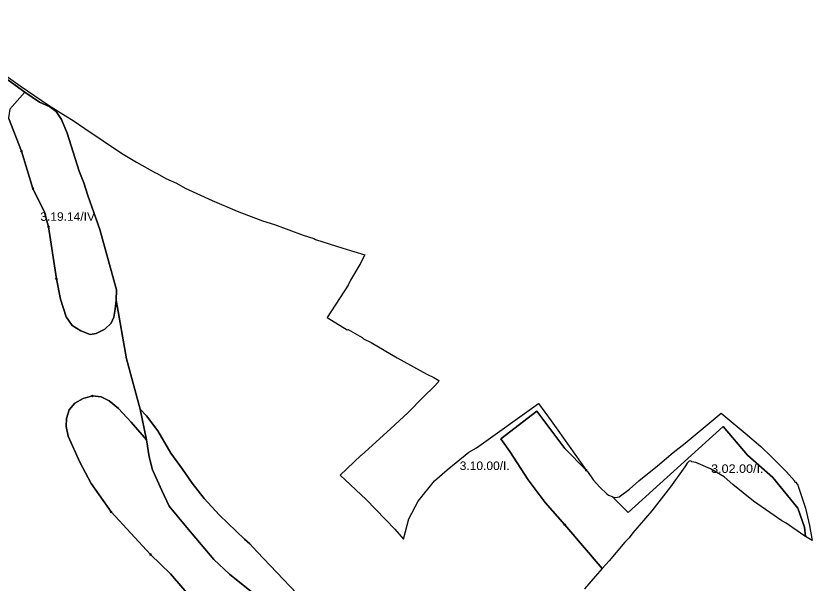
# Model space of a CAD drawing. Extents: x -650455 to -642254, y -1075222 to -1066610.
# Drawn here: x -644416 to -643484, y -1072701 to -1072036 of the extents above; entities that cross this region are included whole.
import ezdxf
from ezdxf.enums import TextEntityAlignment as Align

# ---------------------------------------------------------------- set-up
doc = ezdxf.new("R2010")
doc.units = 0
doc.header["$LTSCALE"] = 4
doc.header["$PDMODE"] = 32
doc.header["$PDSIZE"] = 2
for name, color, linetype, lineweight in [('1', 7, 'Continuous', 25), ('11', 7, 'Continuous', 13), ('13', 7, 'Continuous', 13), ('14', 7, 'Continuous', 13)]:
    doc.layers.add(name, color=color, linetype=linetype, lineweight=lineweight)
doc.layers.add('2', color=7, linetype='Continuous')

msp = doc.modelspace()

# ---------------------------------------------------------------- linework, layer by layer
at = {"layer": '1'}
for points in [[(-644538.207, -1072030.496), (-644520.385, -1072042.196), (-644480.817, -1072072.875), (-644437.149, -1072103.18), (-644405.404, -1072125.733), (-644423.152, -1072145.492), (-644424.551, -1072155.634), (-644409.426, -1072194.802), (-644395.962, -1072238.516), (-644382.411, -1072266.143), (-644377.69, -1072283.279), (-644368.51, -1072344.479), (-644363.526, -1072367.91), (-644357.056, -1072388.717), (-644349.887, -1072398.859), (-644340.095, -1072405.329), (-644329.079, -1072409.525), (-644322.085, -1072408.476), (-644311.769, -1072403.231), (-644304.425, -1072396.061), (-644301.277, -1072389.242), (-644299.529, -1072379.975), (-644298.392, -1072369.308), (-644286.239, -1072437.852)], [(-644438.697, -1072098.552), (-644410.923, -1072118.41), (-644377.621, -1072140.846), (-644357.865, -1072153.546), (-644348.692, -1072158.767), (-644335.287, -1072168.363), (-644292.247, -1072197.151), (-644274.89, -1072207.593), (-644252.594, -1072220.293), (-644250.619, -1072220.858), (-644240.176, -1072226.643), (-644227.758, -1072232.429), (-644217.598, -1072237.932), (-644186.271, -1072252.607), (-644156.637, -1072265.167), (-644127.004, -1072276.455), (-644113.174, -1072280.831), (-644079.59, -1072293.107), (-644067.172, -1072296.917), (-644065.196, -1072298.046), (-644033.064, -1072308.452), (-644007.321, -1072316.245), (-644012.984, -1072327.397), (-644023.991, -1072346.024), (-644026.954, -1072351.811), (-644051.306, -1072389.703)], [(-644286.239, -1072437.852), (-644298.392, -1072369.308), (-644298.305, -1072357.068), (-644317.801, -1072286.426), (-644331.79, -1072246.559), (-644336.423, -1072231.696), (-644342.019, -1072218.058), (-644355.745, -1072173.819), (-644362.564, -1072157.557), (-644368.859, -1072148.465), (-644376.028, -1072142.869), (-644388.268, -1072137.274), (-644405.404, -1072125.733), (-644437.149, -1072103.18)], [(-644423.152, -1072145.492), (-644405.404, -1072125.733), (-644388.268, -1072137.274), (-644376.028, -1072142.869), (-644368.859, -1072148.465), (-644362.564, -1072157.557), (-644355.745, -1072173.819), (-644342.019, -1072218.058), (-644336.423, -1072231.696), (-644331.79, -1072246.559), (-644317.801, -1072286.426), (-644298.305, -1072357.068), (-644298.392, -1072369.308), (-644299.529, -1072379.975), (-644301.277, -1072389.242), (-644304.425, -1072396.061), (-644311.769, -1072403.231), (-644322.085, -1072408.476), (-644329.079, -1072409.525), (-644340.095, -1072405.329), (-644349.887, -1072398.859), (-644357.056, -1072388.717), (-644363.526, -1072367.91), (-644368.51, -1072344.479), (-644377.69, -1072283.279), (-644382.411, -1072266.143), (-644395.962, -1072238.516), (-644409.426, -1072194.802), (-644424.551, -1072155.634)], [(-644051.306, -1072389.703), (-644027.942, -1072403.881), (-644026.672, -1072403.74), (-644010.585, -1072413.194), (-644009.033, -1072414.464), (-644000.002, -1072418.98), (-643969.521, -1072436.761), (-643934.525, -1072455.951), (-643926.622, -1072459.761), (-643920.696, -1072463.432), (-643921.401, -1072465.266), (-643926.058, -1072470.487), (-643938.758, -1072482.623), (-643956.68, -1072500.684), (-643977.282, -1072520.158), (-644011.29, -1072550.922), (-644011.982, -1072551.178), (-644036.381, -1072574.279), (-644005.928, -1072602.71), (-643972.061, -1072637.565), (-643961.833, -1072649.254), (-643955.722, -1072625.442), (-643944.831, -1072604.597), (-643925.552, -1072581.035), (-643910.943, -1072568.102), (-643885.377, -1072547.293), (-643876.387, -1072542.172), (-643804.01, -1072490.458), (-643789.037, -1072510.422), (-643785.368, -1072516.208), (-643781.276, -1072521.428), (-643748.01, -1072568.45), (-643773.195, -1072543.057), (-643805.894, -1072499.343), (-643848.034, -1072531.866), (-643837.543, -1072546.38), (-643816.123, -1072579.777), (-643796.189, -1072606.18), (-643773.108, -1072632.234), (-643729.268, -1072683.464)], [(-644286.239, -1072437.852), (-644270.415, -1072497.128), (-644262.896, -1072532.799), (-644280.783, -1072512.218), (-644295.821, -1072496.306), (-644306.662, -1072487.214), (-644316.279, -1072482.492), (-644326.42, -1072481.443), (-644337.262, -1072484.591), (-644347.053, -1072490.011), (-644353.523, -1072497.705), (-644356.846, -1072507.847), (-644357.02, -1072517.289), (-644354.572, -1072528.48), (-644341.108, -1072559.08), (-644327.819, -1072584.084), (-644304.476, -1072617.307), (-644258.227, -1072667.141), (-644234.796, -1072689.872), (-644186.973, -1072745.651)], [(-644087.515, -1072712.377), (-644133.59, -1072663.941), (-644141.983, -1072654.499), (-644148.278, -1072649.253), (-644177.392, -1072620.927), (-644195.402, -1072601.518), (-644209.565, -1072583.682), (-644221.018, -1072567.071), (-644234.482, -1072548.536), (-644249.695, -1072522.483), (-644262.896, -1072504.647), (-644270.415, -1072497.128), (-644286.239, -1072437.852)], [(-644234.796, -1072689.872), (-644258.227, -1072667.141), (-644304.476, -1072617.307), (-644327.819, -1072584.084), (-644341.108, -1072559.08), (-644354.572, -1072528.48), (-644357.02, -1072517.289), (-644356.846, -1072507.847), (-644353.523, -1072497.705), (-644347.053, -1072490.011), (-644337.262, -1072484.591), (-644326.42, -1072481.443), (-644316.279, -1072482.492), (-644306.662, -1072487.214), (-644295.821, -1072496.306), (-644280.783, -1072512.218), (-644262.896, -1072532.799)], [(-644136.264, -1072714.177), (-644165.902, -1072690.047), (-644184.262, -1072673.086), (-644215.824, -1072635.667), (-644236.282, -1072610.662), (-644245.025, -1072592.302), (-644255.953, -1072567.997), (-644259.8, -1072552.61), (-644262.896, -1072532.799), (-644270.415, -1072497.128), (-644262.896, -1072504.647), (-644249.695, -1072522.483), (-644234.482, -1072548.536), (-644221.018, -1072567.071), (-644209.565, -1072583.682), (-644195.402, -1072601.518), (-644177.392, -1072620.927), (-644148.278, -1072649.253), (-644141.983, -1072654.499), (-644133.59, -1072663.941), (-644087.515, -1072712.377)], [(-643837.543, -1072546.38), (-643848.034, -1072531.866), (-643805.894, -1072499.343), (-643773.195, -1072543.057), (-643748.01, -1072568.45)], [(-643748.01, -1072568.45), (-643747.832, -1072568.701), (-643746.421, -1072570.113), (-643739.789, -1072579.849), (-643732.169, -1072588.175), (-643723.984, -1072596.077), (-643722.009, -1072597.489), (-643717.775, -1072599.322), (-643717.273, -1072599.44), (-643698.794, -1072618.071), (-643587.673, -1072517.179), (-643559.346, -1072550.751), (-643529.446, -1072576.979), (-643500.332, -1072612.825), (-643492.463, -1072635.207), (-643491.082, -1072646.002), (-643493.123, -1072644.762), (-643514.008, -1072630.508), (-643518.947, -1072627.546), (-643552.249, -1072604.544), (-643576.521, -1072585.212), (-643586.681, -1072576.322), (-643602.627, -1072567.008), (-643619.561, -1072559.529), (-643624.217, -1072558.682), (-643625.487, -1072557.272), (-643627.463, -1072557.836), (-643630.003, -1072560.234), (-643632.402, -1072564.467), (-643649.194, -1072588.034), (-643671.208, -1072615.974), (-643693.362, -1072641.657), (-643697.737, -1072647.724), (-643702.817, -1072652.664), (-643721.303, -1072674.677), (-643729.268, -1072683.464), (-643773.108, -1072632.234), (-643796.189, -1072606.18), (-643816.123, -1072579.777), (-643837.543, -1072546.38)], [(-644262.896, -1072532.799), (-644259.8, -1072552.61), (-644255.953, -1072567.997), (-644245.025, -1072592.302), (-644236.282, -1072610.662), (-644215.824, -1072635.667), (-644184.262, -1072673.086), (-644165.902, -1072690.047), (-644136.264, -1072714.177)], [(-643729.268, -1072683.464), (-643734.991, -1072689.776), (-643750.231, -1072707.416)], [(-644186.973, -1072745.651), (-644234.796, -1072689.872)]]:
    msp.add_lwpolyline(points, dxfattribs=at)
msp.add_lwpolyline([(-643590.092, -1072501.685), (-643561.704, -1072525.097), (-643543.642, -1072540.62), (-643531.365, -1072552.332), (-643513.584, -1072570.394), (-643504.13, -1072580.979), (-643503.989, -1072581.824), (-643503.142, -1072582.53), (-643502.437, -1072582.53), (-643501.449, -1072584.365), (-643500.602, -1072584.929), (-643491.43, -1072612.87), (-643486.632, -1072633.191), (-643483.535, -1072650.588), (-643491.082, -1072646.002), (-643492.463, -1072635.207), (-643500.332, -1072612.825), (-643529.446, -1072576.979), (-643559.346, -1072550.751), (-643587.673, -1072517.179), (-643698.794, -1072618.071), (-643717.273, -1072599.44), (-643713.542, -1072600.31), (-643709.45, -1072599.606), (-643697.314, -1072590.715), (-643686.307, -1072580.979), (-643664.717, -1072563.479), (-643646.09, -1072547.534), (-643632.261, -1072536.668)], close=True, dxfattribs=at)
at = {"layer": '11'}
for points in [[(-644348.692, -1072158.767), (-644357.865, -1072153.546), (-644377.621, -1072140.846), (-644410.923, -1072118.41), (-644438.697, -1072098.552)], [(-644437.149, -1072103.18), (-644405.404, -1072125.733), (-644388.268, -1072137.274), (-644376.028, -1072142.869), (-644368.859, -1072148.465), (-644362.564, -1072157.557), (-644355.745, -1072173.819), (-644342.019, -1072218.058), (-644336.423, -1072231.696), (-644331.79, -1072246.559), (-644317.801, -1072286.426), (-644298.305, -1072357.068), (-644298.392, -1072369.308), (-644286.239, -1072437.852), (-644270.415, -1072497.128), (-644262.896, -1072504.647), (-644249.695, -1072522.483), (-644234.482, -1072548.536), (-644221.018, -1072567.071), (-644209.565, -1072583.682), (-644195.402, -1072601.518), (-644177.392, -1072620.927), (-644148.278, -1072649.253), (-644141.983, -1072654.499), (-644133.59, -1072663.941), (-644087.515, -1072712.377)], [(-644005.928, -1072602.71), (-644036.381, -1072574.279), (-644011.982, -1072551.178), (-644011.29, -1072550.922), (-643977.282, -1072520.158), (-643956.68, -1072500.684), (-643938.758, -1072482.623), (-643926.058, -1072470.487), (-643921.401, -1072465.266), (-643920.696, -1072463.432), (-643926.622, -1072459.761), (-643934.525, -1072455.951), (-643969.521, -1072436.761), (-644000.002, -1072418.98), (-644009.033, -1072414.464), (-644010.585, -1072413.194), (-644026.672, -1072403.74), (-644027.942, -1072403.881), (-644051.306, -1072389.703), (-644026.954, -1072351.811), (-644023.991, -1072346.024), (-644012.984, -1072327.397), (-644007.321, -1072316.245), (-644033.064, -1072308.452), (-644065.196, -1072298.046), (-644067.172, -1072296.917), (-644079.59, -1072293.107), (-644113.174, -1072280.831), (-644127.004, -1072276.455), (-644156.637, -1072265.167), (-644186.271, -1072252.607), (-644217.598, -1072237.932), (-644227.758, -1072232.429), (-644240.176, -1072226.643), (-644250.619, -1072220.858), (-644252.594, -1072220.293), (-644274.89, -1072207.593), (-644292.247, -1072197.151), (-644335.287, -1072168.363), (-644348.692, -1072158.767)], [(-643750.231, -1072707.416), (-643734.991, -1072689.776), (-643729.268, -1072683.464), (-643773.108, -1072632.234), (-643796.189, -1072606.18), (-643816.123, -1072579.777), (-643837.543, -1072546.38), (-643848.034, -1072531.866), (-643805.894, -1072499.343), (-643773.195, -1072543.057), (-643748.01, -1072568.45), (-643781.276, -1072521.428), (-643785.368, -1072516.208), (-643789.037, -1072510.422), (-643804.01, -1072490.458), (-643876.387, -1072542.172), (-643885.377, -1072547.293), (-643910.943, -1072568.102), (-643925.552, -1072581.035), (-643944.831, -1072604.597), (-643955.722, -1072625.442), (-643961.833, -1072649.254), (-643972.061, -1072637.565), (-644005.928, -1072602.71)], [(-643748.01, -1072568.45), (-643773.195, -1072543.057), (-643805.894, -1072499.343), (-643848.034, -1072531.866), (-643837.543, -1072546.38), (-643816.123, -1072579.777), (-643796.189, -1072606.18), (-643773.108, -1072632.234)], [(-643773.108, -1072632.234), (-643729.268, -1072683.464), (-643721.303, -1072674.677), (-643702.817, -1072652.664), (-643697.737, -1072647.724), (-643693.362, -1072641.657), (-643671.208, -1072615.974), (-643649.194, -1072588.034), (-643632.402, -1072564.467), (-643630.003, -1072560.234), (-643627.463, -1072557.836), (-643625.487, -1072557.272), (-643624.217, -1072558.682), (-643619.561, -1072559.529), (-643602.627, -1072567.008), (-643586.681, -1072576.322), (-643576.521, -1072585.212), (-643552.249, -1072604.544), (-643518.947, -1072627.546), (-643514.008, -1072630.508), (-643493.123, -1072644.762), (-643491.082, -1072646.002), (-643492.463, -1072635.207), (-643500.332, -1072612.825), (-643529.446, -1072576.979), (-643559.346, -1072550.751), (-643587.673, -1072517.179), (-643698.794, -1072618.071), (-643717.273, -1072599.44), (-643717.775, -1072599.322), (-643722.009, -1072597.489), (-643723.984, -1072596.077), (-643732.169, -1072588.175), (-643739.789, -1072579.849), (-643746.421, -1072570.113), (-643747.832, -1072568.701), (-643748.01, -1072568.45)]]:
    msp.add_lwpolyline(points, dxfattribs=at)
msp.add_lwpolyline([(-643686.307, -1072580.979), (-643697.314, -1072590.715), (-643709.45, -1072599.606), (-643713.542, -1072600.31), (-643717.273, -1072599.44), (-643698.794, -1072618.071), (-643587.673, -1072517.179), (-643559.346, -1072550.751), (-643529.446, -1072576.979), (-643500.332, -1072612.825), (-643492.463, -1072635.207), (-643491.082, -1072646.002), (-643483.535, -1072650.588), (-643486.632, -1072633.191), (-643491.43, -1072612.87), (-643500.602, -1072584.929), (-643501.449, -1072584.365), (-643502.437, -1072582.53), (-643503.142, -1072582.53), (-643503.989, -1072581.824), (-643504.13, -1072580.979), (-643513.584, -1072570.394), (-643531.365, -1072552.332), (-643543.642, -1072540.62), (-643561.704, -1072525.097), (-643590.092, -1072501.685), (-643632.261, -1072536.668), (-643646.09, -1072547.534), (-643664.717, -1072563.479)], close=True, dxfattribs=at)
for p in [(-643748.01, -1072568.45), (-643773.108, -1072632.234)]:
    msp.add_point(p, dxfattribs=at)
at = {"layer": '13'}
for points in [[(-644424.551, -1072155.634), (-644423.152, -1072145.492), (-644405.404, -1072125.733), (-644437.149, -1072103.18), (-644480.817, -1072072.875), (-644520.385, -1072042.196), (-644538.207, -1072030.496)], [(-644326.42, -1072481.443), (-644316.279, -1072482.492), (-644306.662, -1072487.214), (-644295.821, -1072496.306), (-644280.783, -1072512.218), (-644262.896, -1072532.799), (-644270.415, -1072497.128), (-644286.239, -1072437.852), (-644298.392, -1072369.308), (-644299.529, -1072379.975), (-644301.277, -1072389.242), (-644304.425, -1072396.061), (-644311.769, -1072403.231), (-644322.085, -1072408.476), (-644329.079, -1072409.525), (-644340.095, -1072405.329), (-644349.887, -1072398.859), (-644357.056, -1072388.717), (-644363.526, -1072367.91), (-644368.51, -1072344.479), (-644377.69, -1072283.279), (-644382.411, -1072266.143), (-644395.962, -1072238.516), (-644409.426, -1072194.802), (-644424.551, -1072155.634)], [(-644304.476, -1072617.307), (-644327.819, -1072584.084), (-644341.108, -1072559.08), (-644354.572, -1072528.48), (-644357.02, -1072517.289), (-644356.846, -1072507.847), (-644353.523, -1072497.705), (-644347.053, -1072490.011), (-644337.262, -1072484.591), (-644326.42, -1072481.443)], [(-644087.515, -1072712.377), (-644133.59, -1072663.941), (-644141.983, -1072654.499), (-644148.278, -1072649.253), (-644177.392, -1072620.927), (-644195.402, -1072601.518), (-644209.565, -1072583.682), (-644221.018, -1072567.071), (-644234.482, -1072548.536), (-644249.695, -1072522.483), (-644262.896, -1072504.647), (-644270.415, -1072497.128), (-644262.896, -1072532.799), (-644259.8, -1072552.61), (-644255.953, -1072567.997), (-644245.025, -1072592.302), (-644236.282, -1072610.662), (-644215.824, -1072635.667), (-644184.262, -1072673.086), (-644165.902, -1072690.047), (-644136.264, -1072714.177)], [(-644186.973, -1072745.651), (-644234.796, -1072689.872), (-644258.227, -1072667.141), (-644304.476, -1072617.307)]]:
    msp.add_lwpolyline(points, dxfattribs=at)
for p in [(-644326.42, -1072481.443), (-644304.476, -1072617.307)]:
    msp.add_point(p, dxfattribs=at)
at = {"layer": '14'}
for p, q in [((-644409.426, -1072194.802), (-644395.962, -1072238.516)), ((-644377.69, -1072283.279), (-644368.51, -1072344.479))]:
    msp.add_line(p, q, dxfattribs=at)
for points in [[(-644368.51, -1072344.479), (-644363.526, -1072367.91), (-644357.056, -1072388.717), (-644349.887, -1072398.859), (-644340.095, -1072405.329), (-644329.079, -1072409.525), (-644322.085, -1072408.476), (-644311.769, -1072403.231), (-644304.425, -1072396.061), (-644301.277, -1072389.242), (-644299.529, -1072379.975), (-644298.392, -1072369.308), (-644298.305, -1072357.068), (-644317.801, -1072286.426), (-644331.79, -1072246.559), (-644336.423, -1072231.696), (-644342.019, -1072218.058), (-644355.745, -1072173.819), (-644362.564, -1072157.557), (-644368.859, -1072148.465), (-644376.028, -1072142.869), (-644388.268, -1072137.274), (-644405.404, -1072125.733), (-644423.152, -1072145.492)], [(-644424.551, -1072155.634), (-644409.426, -1072194.802)], [(-644395.962, -1072238.516), (-644382.411, -1072266.143), (-644377.69, -1072283.279)], [(-644136.264, -1072714.177), (-644165.902, -1072690.047), (-644184.262, -1072673.086), (-644215.824, -1072635.667), (-644236.282, -1072610.662), (-644245.025, -1072592.302), (-644255.953, -1072567.997), (-644259.8, -1072552.61), (-644262.896, -1072532.799), (-644280.783, -1072512.218), (-644295.821, -1072496.306), (-644306.662, -1072487.214), (-644316.279, -1072482.492), (-644326.42, -1072481.443), (-644337.262, -1072484.591), (-644347.053, -1072490.011), (-644353.523, -1072497.705), (-644356.846, -1072507.847), (-644357.02, -1072517.289), (-644354.572, -1072528.48), (-644341.108, -1072559.08), (-644327.819, -1072584.084), (-644304.476, -1072617.307), (-644258.227, -1072667.141)], [(-644258.227, -1072667.141), (-644234.796, -1072689.872), (-644186.973, -1072745.651), (-644155.761, -1072787.617), (-644142.471, -1072800.381), (-644127.172, -1072809.824)]]:
    msp.add_lwpolyline(points, dxfattribs=at)
for p in [(-644409.426, -1072194.802), (-644395.962, -1072238.516), (-644377.69, -1072283.279), (-644368.51, -1072344.479), (-644258.227, -1072667.141)]:
    msp.add_point(p, dxfattribs=at)

# ---------------------------------------------------------------- texts
at = {"layer": '2'}
for s, width, p in [('3.19.14/IV.', 1.05, (-644353.405, -1072276.346)), ('3.10.00/I.', 1.05, (-643866.905, -1072568.186)), ('3.02.00/I.', 1.1, (-643571.103, -1072571.603))]:
    msp.add_text(s, height=10, dxfattribs=dict(at, width=width)).set_placement(p, align=Align.CENTER)

doc.saveas('drawing.dxf')
